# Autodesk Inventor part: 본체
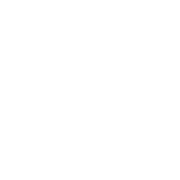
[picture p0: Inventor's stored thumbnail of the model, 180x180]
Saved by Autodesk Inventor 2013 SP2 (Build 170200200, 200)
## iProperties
Created: 2024-08
Part Number: 본체
Material: Generic
Document SubType Name: Modeling
Designer: a
Density: 1 g/cm^3
Author: a
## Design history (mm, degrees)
sketch "스케치1"
  geometry: C1 r 71 at (0, 0); 1 further point
  constraints: 1 centre point, 1 coincident
  dimensions: "d0" = 142 diameter of C1
extrude "돌출1" new body sketch "스케치1" distance "d2" = 20; taper "d3" = 0 deg
fillet "모깎기1" dims "d4" = 6
sketch "스케치2"
  geometry: C1 r 65 at (0, 0) reference
sketch "스케치3"
  geometry: C1 r 71 at (0, 0) reference
node "솔리드1"
